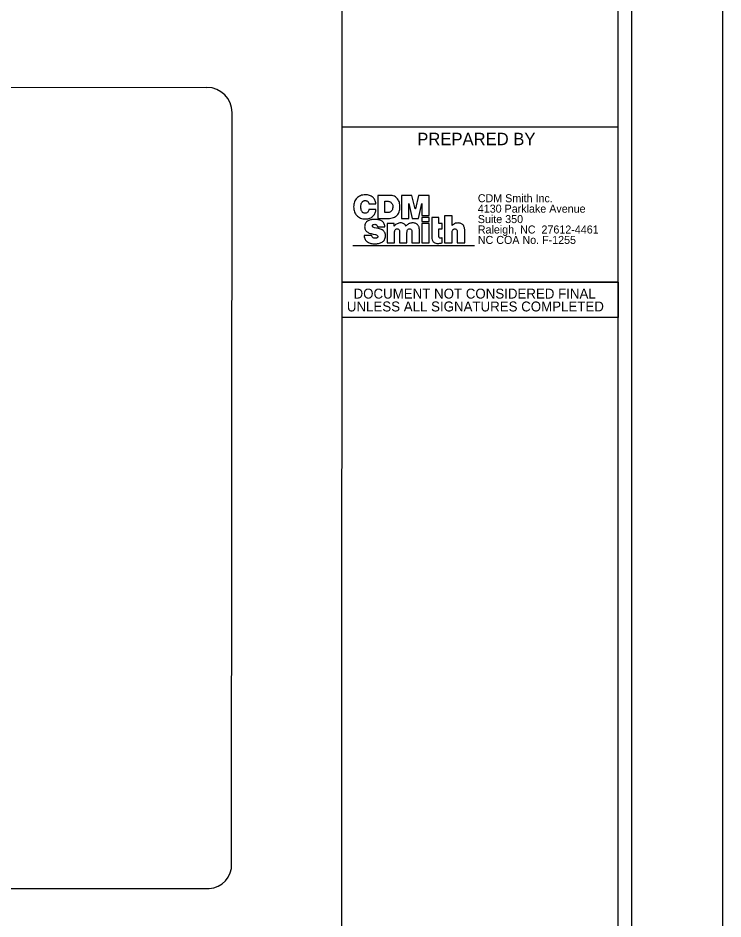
# Model space of a CAD drawing. Extents: x -63 to 3072, y 0 to 1100.
# Drawn here: x 1444.6 to 1700, y 447.2 to 773.6 of the extents above; entities that cross this region are included whole.
import ezdxf

# ---------------------------------------------------------------- set-up
doc = ezdxf.new("R2010")
doc.units = 0
for name, color, linetype in [('Scratch_Level_0', 7, 'Continuous'), ('Sheet Block Title CELL', 7, 'Continuous'), ('Sheet_Plan_CELL', 7, 'Continuous'), ('Sheet_RDY_PE_Seal_Cell', 7, 'Continuous')]:
    doc.layers.add(name, color=color, linetype=linetype)

msp = doc.modelspace()

# ---------------------------------------------------------------- linework, layer by layer
at = {"layer": 'Scratch_Level_0'}
msp.add_line((1699.98, 0), (1699.98, 1100), dxfattribs=at)
at = {"layer": 'Sheet Block Title CELL'}
msp.add_line((1565.85, 691.15), (1610.01, 691.15), dxfattribs=at)
for points in [[(1569.12, 703.6), (1569.04, 703.77), (1568.98, 703.94), (1568.87, 704.34), (1568.81, 704.73), (1568.78, 705.16), (1568.81, 705.59), (1568.87, 705.98), (1568.98, 706.38), (1569.04, 706.55), (1569.12, 706.72), (1569.23, 706.89), (1569.35, 707.04), (1569.46, 707.15), (1569.63, 707.26), (1569.77, 707.35), (1569.97, 707.41), (1570.17, 707.43), (1570.37, 707.46), (1570.57, 707.43), (1570.74, 707.41), (1570.88, 707.38), (1571.02, 707.32), (1571.17, 707.23), (1571.25, 707.15), (1571.42, 706.95), (1571.56, 706.75), (1571.65, 706.55), (1571.71, 706.35), (1571.73, 706.24), (1574.24, 706.24), (1574.18, 706.61), (1574.09, 706.98), (1574.01, 707.32), (1573.87, 707.63), (1573.72, 707.92), (1573.55, 708.2), (1573.35, 708.46), (1573.13, 708.66), (1572.87, 708.85), (1572.59, 709.05), (1572.3, 709.2), (1571.99, 709.31), (1571.62, 709.42), (1571.25, 709.48), (1570.85, 709.54), (1570.46, 709.54), (1569.97, 709.54), (1569.52, 709.45), (1569.09, 709.37), (1568.69, 709.22), (1568.33, 709.05), (1567.98, 708.85), (1567.64, 708.6), (1567.36, 708.34), (1567.1, 708.03), (1566.88, 707.72), (1566.68, 707.35), (1566.51, 706.95), (1566.36, 706.55), (1566.28, 706.1), (1566.22, 705.64), (1566.19, 705.16), (1566.22, 704.71), (1566.28, 704.25), (1566.36, 703.83), (1566.48, 703.43), (1566.65, 703.06), (1566.82, 702.69), (1567.05, 702.35), (1567.3, 702.03), (1567.59, 701.75), (1567.93, 701.52), (1568.27, 701.3), (1568.64, 701.13), (1569.04, 700.98), (1569.49, 700.87), (1569.94, 700.81), (1570.46, 700.78), (1570.88, 700.78), (1571.31, 700.87), (1571.71, 700.96), (1572.08, 701.1), (1572.42, 701.24), (1572.73, 701.44), (1573.01, 701.64), (1573.27, 701.89), (1573.5, 702.15), (1573.7, 702.4), (1573.87, 702.72), (1574.01, 703), (1574.12, 703.31), (1574.21, 703.63), (1574.26, 703.94), (1574.26, 704.25), (1571.73, 704.25), (1571.68, 703.97), (1571.59, 703.71), (1571.48, 703.48), (1571.34, 703.26), (1571.14, 703.09), (1570.94, 702.97), (1570.68, 702.89), (1570.37, 702.86), (1570.17, 702.89), (1569.97, 702.92), (1569.77, 702.97), (1569.63, 703.06), (1569.46, 703.17), (1569.35, 703.29), (1569.23, 703.43), (1569.12, 703.6)], [(1582.96, 704.71), (1582.96, 705.16), (1582.96, 705.56), (1582.93, 705.96), (1582.84, 706.35), (1582.76, 706.72), (1582.65, 707.06), (1582.5, 707.43), (1582.33, 707.75), (1582.13, 708.06), (1581.88, 708.34), (1581.62, 708.57), (1581.31, 708.8), (1580.97, 709), (1580.57, 709.14), (1580.15, 709.25), (1579.69, 709.31), (1579.18, 709.34), (1574.95, 709.34), (1574.95, 700.98), (1578.7, 700.98), (1579.21, 700.98), (1579.72, 701.04), (1580.17, 701.15), (1580.6, 701.27), (1580.97, 701.44), (1581.34, 701.64), (1581.65, 701.86), (1581.94, 702.12), (1582.16, 702.4), (1582.39, 702.72), (1582.56, 703.06), (1582.7, 703.43), (1582.82, 703.82), (1582.9, 704.25), (1582.96, 704.71)], [(1586.17, 706.35), (1586.23, 706.35), (1587.36, 700.98), (1589.64, 700.98), (1590.86, 706.35), (1590.91, 706.35), (1590.91, 702.03), (1593.56, 702.03), (1593.56, 709.34), (1589.75, 709.34), (1588.56, 704.42), (1588.53, 704.42), (1587.33, 709.34), (1583.56, 709.34), (1583.56, 700.98), (1586.17, 700.98), (1586.17, 706.35)], [(1577.53, 707.21), (1578.36, 707.21), (1578.7, 707.18), (1578.98, 707.15), (1579.24, 707.06), (1579.46, 706.95), (1579.66, 706.84), (1579.83, 706.69), (1579.95, 706.55), (1580.06, 706.41), (1580.17, 706.24), (1580.23, 706.07), (1580.34, 705.73), (1580.37, 705.44), (1580.4, 705.22), (1580.37, 704.9), (1580.32, 704.56), (1580.23, 704.19), (1580.15, 704.02), (1580.06, 703.88), (1579.97, 703.71), (1579.83, 703.57), (1579.69, 703.46), (1579.52, 703.34), (1579.32, 703.26), (1579.09, 703.17), (1578.84, 703.14), (1578.55, 703.11), (1577.53, 703.11), (1577.53, 707.21)], [(1606.29, 697.8), (1606.17, 698.06), (1606.09, 698.28), (1605.95, 698.48), (1605.8, 698.65), (1605.63, 698.82), (1605.46, 698.94), (1605.26, 699.05), (1605.04, 699.16), (1604.81, 699.22), (1604.58, 699.28), (1604.33, 699.31), (1604.07, 699.33), (1603.73, 699.31), (1603.42, 699.28), (1603.1, 699.22), (1602.76, 699.08), (1602.54, 698.94), (1602.34, 698.79), (1602.11, 698.6), (1601.88, 698.37), (1601.88, 701.95), (1599.15, 701.95), (1599.15, 692.09), (1601.88, 692.09), (1601.88, 695.5), (1601.88, 695.92), (1601.94, 696.32), (1602.05, 696.61), (1602.11, 696.72), (1602.17, 696.83), (1602.28, 696.98), (1602.45, 697.09), (1602.62, 697.18), (1602.79, 697.2), (1603.02, 697.2), (1603.19, 697.15), (1603.33, 697.06), (1603.47, 696.92), (1603.59, 696.78), (1603.64, 696.55), (1603.7, 696.29), (1603.7, 695.98), (1603.7, 692.09), (1606.43, 692.09), (1606.43, 696.58), (1606.43, 696.92), (1606.4, 697.23), (1606.34, 697.54), (1606.29, 697.8)], [(1577.73, 695.02), (1577.7, 695.24), (1577.64, 695.44), (1577.59, 695.67), (1577.5, 695.84), (1577.42, 696.01), (1577.3, 696.18), (1577.19, 696.32), (1576.91, 696.58), (1576.59, 696.81), (1576.28, 696.98), (1575.91, 697.12), (1575.54, 697.23), (1575.17, 697.32), (1574.43, 697.49), (1573.81, 697.6), (1573.55, 697.69), (1573.33, 697.77), (1573.21, 697.83), (1573.1, 697.91), (1573.01, 698.03), (1572.98, 698.2), (1573.01, 698.4), (1573.07, 698.54), (1573.16, 698.65), (1573.27, 698.74), (1573.41, 698.8), (1573.58, 698.82), (1573.89, 698.85), (1574.06, 698.82), (1574.24, 698.8), (1574.38, 698.71), (1574.52, 698.6), (1574.66, 698.48), (1574.77, 698.34), (1574.83, 698.17), (1574.86, 697.97), (1577.53, 697.97), (1577.5, 698.37), (1577.42, 698.71), (1577.3, 699.02), (1577.16, 699.31), (1576.96, 699.53), (1576.76, 699.76), (1576.54, 699.96), (1576.25, 700.1), (1576, 700.24), (1575.68, 700.36), (1575.4, 700.44), (1575.09, 700.53), (1574.75, 700.59), (1574.43, 700.61), (1573.81, 700.64), (1573.21, 700.61), (1572.9, 700.56), (1572.59, 700.53), (1572.27, 700.44), (1571.99, 700.36), (1571.71, 700.24), (1571.42, 700.1), (1571.17, 699.93), (1570.91, 699.73), (1570.71, 699.51), (1570.54, 699.28), (1570.4, 698.99), (1570.29, 698.68), (1570.2, 698.34), (1570.17, 697.94), (1570.2, 697.69), (1570.23, 697.43), (1570.29, 697.2), (1570.37, 696.98), (1570.46, 696.78), (1570.6, 696.58), (1570.74, 696.41), (1570.91, 696.24), (1571.11, 696.1), (1571.34, 695.95), (1571.59, 695.81), (1571.88, 695.7), (1572.19, 695.58), (1572.53, 695.47), (1573.33, 695.3), (1574.15, 695.13), (1574.43, 695.04), (1574.63, 694.96), (1574.77, 694.85), (1574.86, 694.73), (1574.92, 694.59), (1574.95, 694.42), (1574.92, 694.25), (1574.83, 694.11), (1574.72, 693.99), (1574.58, 693.91), (1574.43, 693.85), (1574.26, 693.79), (1573.95, 693.77), (1573.7, 693.79), (1573.47, 693.82), (1573.3, 693.91), (1573.16, 693.99), (1573.01, 694.16), (1572.9, 694.36), (1572.84, 694.53), (1572.81, 694.76), (1570, 694.76), (1570.03, 694.36), (1570.11, 693.99), (1570.23, 693.68), (1570.37, 693.37), (1570.54, 693.11), (1570.77, 692.86), (1571, 692.63), (1571.25, 692.46), (1571.54, 692.29), (1571.85, 692.15), (1572.16, 692.03), (1572.47, 691.95), (1572.81, 691.86), (1573.16, 691.83), (1573.5, 691.81), (1573.84, 691.78), (1574.55, 691.81), (1574.89, 691.86), (1575.23, 691.92), (1575.57, 692), (1575.88, 692.12), (1576.2, 692.23), (1576.48, 692.4), (1576.76, 692.57), (1576.99, 692.8), (1577.22, 693.03), (1577.39, 693.31), (1577.53, 693.62), (1577.64, 693.97), (1577.73, 694.33), (1577.73, 694.76), (1577.73, 695.02)], [(1581.08, 696.44), (1581.14, 696.64), (1581.25, 696.83), (1581.37, 696.98), (1581.51, 697.09), (1581.71, 697.18), (1581.96, 697.2), (1582.22, 697.18), (1582.45, 697.09), (1582.59, 696.98), (1582.7, 696.81), (1582.76, 696.61), (1582.82, 696.41), (1582.84, 696.18), (1582.84, 695.93), (1582.84, 692.12), (1585.52, 692.12), (1585.52, 695.93), (1585.54, 696.18), (1585.57, 696.44), (1585.63, 696.64), (1585.74, 696.83), (1585.86, 696.98), (1586, 697.09), (1586.2, 697.18), (1586.45, 697.2), (1586.71, 697.18), (1586.94, 697.09), (1587.08, 696.98), (1587.19, 696.81), (1587.25, 696.61), (1587.31, 696.41), (1587.33, 696.18), (1587.33, 695.93), (1587.33, 692.12), (1590, 692.12), (1590, 696.95), (1589.98, 697.37), (1589.95, 697.6), (1589.89, 697.8), (1589.83, 698), (1589.72, 698.2), (1589.61, 698.4), (1589.49, 698.57), (1589.32, 698.74), (1589.15, 698.88), (1588.95, 699.02), (1588.73, 699.14), (1588.5, 699.22), (1588.21, 699.28), (1587.93, 699.33), (1587.59, 699.33), (1587.28, 699.33), (1586.99, 699.31), (1586.74, 699.25), (1586.48, 699.19), (1586.28, 699.11), (1586.08, 699.02), (1585.77, 698.82), (1585.54, 698.62), (1585.37, 698.45), (1585.2, 698.23), (1585.03, 698.48), (1584.86, 698.71), (1584.63, 698.91), (1584.41, 699.05), (1584.12, 699.16), (1583.87, 699.28), (1583.58, 699.34), (1583.27, 699.34), (1582.93, 699.34), (1582.59, 699.28), (1582.28, 699.19), (1581.96, 699.08), (1581.68, 698.94), (1581.42, 698.74), (1581.2, 698.51), (1580.94, 698.19), (1580.94, 699.16), (1578.36, 699.16), (1578.35, 692.12), (1581.03, 692.12), (1581.03, 695.93), (1581.05, 696.18), (1581.08, 696.44)], [(1593.56, 701.32), (1590.91, 701.32), (1590.91, 699.87), (1593.56, 699.87), (1593.56, 701.32)], [(1593.56, 699.16), (1590.91, 699.16), (1590.91, 692.09), (1593.56, 692.09), (1593.56, 699.16)], [(1598.25, 699.16), (1597.08, 699.16), (1597.08, 701.32), (1594.47, 701.32), (1594.47, 699.16), (1594.47, 697.18), (1594.47, 694.7), (1594.47, 694.16), (1594.52, 693.68), (1594.61, 693.28), (1594.72, 692.94), (1594.86, 692.69), (1595.01, 692.49), (1595.2, 692.34), (1595.4, 692.2), (1595.66, 692.09), (1595.97, 692), (1596.34, 691.95), (1596.8, 691.95), (1597.11, 691.95), (1597.48, 692), (1597.88, 692.06), (1598.24, 692.17), (1598.24, 693.94), (1598.13, 693.91), (1597.93, 693.88), (1597.53, 693.85), (1597.39, 693.88), (1597.28, 693.96), (1597.22, 694.02), (1597.17, 694.08), (1597.14, 694.16), (1597.11, 694.31), (1597.08, 694.67), (1597.08, 697.18), (1598.25, 697.18), (1598.25, 699.16)]]:
    msp.add_lwpolyline(points, dxfattribs=at)
at = {"layer": 'Sheet_Plan_CELL'}
for p, q in [((1661.97, 734.06), (1561.97, 734.06)), ((1662.03, 677.87), (1562.03, 677.87))]:
    msp.add_line(p, q, dxfattribs=at)
msp.add_lwpolyline([(1562.03, 677.87), (1662.03, 677.87), (1662.03, 665.13), (1562.03, 665.13)], close=True, dxfattribs=at)
at = {"layer": 'Sheet_RDY_PE_Seal_Cell'}
for p, q in [((1561.97, 39.96), (1562, 1059.93)), ((1662, 39.96), (1662, 1059.91)), ((1667, 39.99), (1667, 1059.91)), ((1365.97, 748.52), (1513.07, 748.45)), ((1521.98, 467.26), (1522.15, 739.36)), ((1039.28, 458.4), (1513.82, 458.18))]:
    msp.add_line(p, q, dxfattribs=at)
for centre, radius, start, end in [((1513.06, 739.36), 9.09, 359.9734, 89.9734), ((1513.36, 466.8), 8.64, 273.0459, 3.0459)]:
    msp.add_arc(centre, radius, start, end, dxfattribs=at)

# ---------------------------------------------------------------- texts
at = {"layer": 'Sheet Block Title CELL'}
for s, height, p in [('CDM Smith Inc.', 2.9003, (1611.18, 706.85)), ('4130 Parklake Avenue', 2.9003, (1611.18, 703.07)), ('Suite 350', 2.9, (1611.18, 699.29)), ('Raleigh, NC  27612-4461', 2.9003, (1611.18, 695.52)), ('NC COA No. F-1255', 2.9003, (1611.18, 691.74))]:
    msp.add_text(s, height=height, rotation=359.9982, dxfattribs=at).set_placement(p)
at = {"layer": 'Sheet_Plan_CELL'}
for s, height, p in [('PREPARED BY', 4.5, (1589.25, 727.51)), ('DOCUMENT NOT CONSIDERED FINAL', 3.6, (1566.18, 671.94)), ('UNLESS ALL SIGNATURES COMPLETED', 3.6, (1563.75, 667.28))]:
    msp.add_text(s, height=height, rotation=0, dxfattribs=at).set_placement(p)

doc.saveas('drawing.dxf')
